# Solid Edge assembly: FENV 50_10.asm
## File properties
Title: Zylinder
Author: bmolnar
Template: iso assembly.asm
Last saved by: bmolnar
Revision: 8
Application: Solid Edge
Username: bmolnar
Dokumentum tartalom típus: 1
Document Number: FENV 50/10
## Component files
Kit_1.par
Profilrohr.par
Kit_2.par
Kolbenstange.par
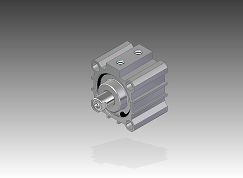
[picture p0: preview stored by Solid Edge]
